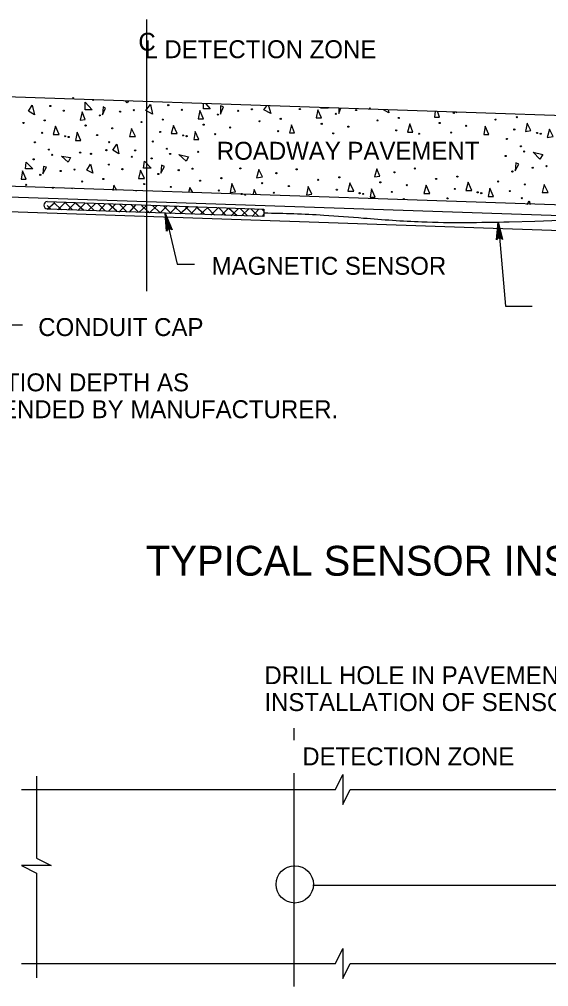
# Model space of a CAD drawing. Extents: x 2709 to 3899, y 22 to 1210.
# Drawn here: x 2819.9 to 2908.4, y 167.3 to 329.2 of the extents above; entities that cross this region are included whole.
import ezdxf

# ---------------------------------------------------------------- set-up
doc = ezdxf.new("R2010")
doc.units = 0
doc.layers.add('2', color=7, linetype='Continuous')
doc.layers.add('3', color=7, linetype='Continuous')

# ---------------------------------------------------------------- blocks, each defined once
blk = doc.blocks.new('RARROW')
at = {"layer": '3'}
blk.add_lwpolyline([(-2.2695, 0.285), (-2.184875, 0.12075), (0, 0), (-2.2695, 0.285), (-2.38575, 0.384625), (0, 0), (-2.183125, -0.108), (-2.262875, -0.2705), (0, 0), (-2.38575, -0.379125), (-2.262875, -0.2705)], dxfattribs=at)

msp = doc.modelspace()

# ---------------------------------------------------------------- linework, layer by layer
at = {"layer": '2'}
for p, q in [((2841.15, 329.17), (2841.15, 283.67)), ((2816.4, 299.54), (3040.28, 291.92)), ((2816.4, 297.04), (3040.28, 289.42)), ((2844.26, 296.74), (2846.28, 288.17)), ((2899.93, 295.3), (2901.15, 281.17)), ((2846.28, 288.17), (2849.15, 288.17)), ((2901.15, 281.17), (2905.65, 281.17)), ((2817.15, 278.04), (2820.4, 278.04)), ((2865.85, 208.54), (2865.85, 210.54)), ((2865.85, 167.29), (2865.85, 203.04)), ((2868.97, 184.29), (3023.97, 184.29))]:
    msp.add_line(p, q, dxfattribs=at)
for points in [[(2801.15, 316.79), (2948.65, 311.79), (2948.65, 296.79), (2801.15, 301.79), (2801.15, 301.79)], [(2837.9, 315.17), (2837.65, 315.54)], [(2838.15, 315.54), (2837.9, 315.17)], [(2850.65, 314.17), (2850.65, 315.04)], [(2851.78, 314.17), (2850.65, 314.17)], [(2851.03, 315.04), (2851.78, 314.17)], [(2860.78, 314.04), (2861.28, 314.67)], [(2861.53, 314.67), (2861.9, 313.42)], [(2870.28, 314.29), (2870.28, 314.42)], [(2871.53, 314.29), (2870.28, 314.29)], [(2871.53, 314.42), (2871.53, 314.29)], [(2873.28, 314.29), (2873.28, 313.42)], [(2873.28, 313.42), (2873.65, 314.29)], [(2861.9, 313.42), (2860.78, 314.04)], [(2881.65, 313.54), (2880.78, 314.04)], [(2881.53, 314.04), (2881.65, 313.54)], [(2889.4, 313.79), (2889.28, 312.79)], [(2889.28, 312.79), (2890.15, 312.79)], [(2890.15, 312.79), (2889.78, 313.79)], [(2892.9, 313.67), (2892.9, 313.54)], [(2892.9, 313.54), (2893.03, 313.67)], [(2835.65, 301.42), (2835.53, 300.54)], [(2836.15, 300.54), (2835.65, 301.42)], [(2855.4, 301.67), (2855.15, 300.17)], [(2856.03, 300.29), (2855.4, 301.67)], [(2868.15, 301.17), (2867.9, 299.79)], [(2868.78, 299.92), (2868.15, 301.17)], [(2828.65, 300.92), (2828.65, 300.79)], [(2828.78, 300.79), (2828.65, 300.92)], [(2839.4, 300.54), (2839.4, 300.42)], [(2839.4, 300.42), (2839.4, 300.54)], [(2848.4, 301.04), (2848.15, 300.17)], [(2848.9, 300.17), (2848.4, 301.04)], [(2855.15, 300.17), (2856.03, 300.29)], [(2859.15, 300.67), (2858.9, 299.79)], [(2859.53, 299.79), (2859.15, 300.67)], [(2867.9, 299.79), (2868.78, 299.92)], [(2878.78, 300.79), (2878.53, 299.42)], [(2879.4, 299.42), (2878.78, 300.79)], [(2824.53, 298.67), (2860.78, 297.42), (2860.78, 296.17), (2824.53, 297.42), (2824.53, 297.42)], [(2824.53, 297.42), (2825.78, 298.54)], [(2825.15, 297.42), (2824.53, 298.04)], [(2826.9, 297.29), (2825.65, 298.54)], [(2826.28, 297.29), (2827.53, 298.54)], [(2828.78, 297.29), (2827.53, 298.54)], [(2828.03, 297.29), (2829.15, 298.42)], [(2830.65, 297.17), (2829.28, 298.42)], [(2829.65, 297.17), (2830.9, 298.42)], [(2832.4, 297.17), (2831.15, 298.42)], [(2831.4, 297.17), (2832.65, 298.42)], [(2834.28, 297.04), (2833.03, 298.29)], [(2833.15, 297.04), (2834.28, 298.29)], [(2834.78, 297.04), (2836.03, 298.29)], [(2836.15, 297.04), (2834.78, 298.29)], [(2836.53, 296.92), (2837.78, 298.17)], [(2837.9, 296.92), (2836.65, 298.17)], [(2838.28, 296.92), (2839.4, 298.17)], [(2839.78, 296.92), (2838.53, 298.17)], [(2839.9, 296.92), (2841.15, 298.04)], [(2841.65, 296.79), (2840.28, 298.04)], [(2841.65, 296.79), (2842.9, 298.04)], [(2843.4, 296.79), (2842.15, 298.04)], [(2843.4, 296.79), (2844.53, 297.92)], [(2845.28, 296.67), (2844.03, 297.92)], [(2845.03, 296.67), (2846.28, 297.92)], [(2847.03, 296.67), (2845.78, 297.92)], [(2878.53, 299.42), (2879.4, 299.42)], [(2904.78, 298.17), (2905.15, 298.79)], [(2905.15, 298.79), (2905.28, 298.17)], [(2846.78, 296.67), (2848.03, 297.79)], [(2848.9, 296.54), (2847.65, 297.79)], [(2848.53, 296.54), (2849.65, 297.79)], [(2850.78, 296.54), (2849.4, 297.79)], [(2850.15, 296.54), (2851.4, 297.67)], [(2852.53, 296.42), (2851.28, 297.67)], [(2851.9, 296.42), (2853.15, 297.67)], [(2854.4, 296.42), (2853.15, 297.67)], [(2853.65, 296.42), (2854.78, 297.54)], [(2856.28, 296.29), (2854.9, 297.54)], [(2855.28, 296.29), (2856.53, 297.54)], [(2858.03, 296.29), (2856.78, 297.54)], [(2857.03, 296.29), (2858.28, 297.54)], [(2859.9, 296.17), (2858.65, 297.42)], [(2858.78, 296.17), (2859.9, 297.42)], [(2860.78, 297.04), (2860.4, 297.42)], [(2860.53, 296.17), (2860.78, 296.54)], [(2820.22, 200.29), (2872.72, 200.29), (2873.97, 202.79), (2873.97, 197.79), (2875.22, 200.29), (2925.22, 200.29), (2926.47, 202.79), (2926.47, 197.79), (2927.72, 200.29), (2977.72, 200.29), (2978.97, 202.79), (2978.97, 197.79), (2980.22, 200.29), (3026.47, 200.29)], [(2822.72, 202.54), (2822.72, 188.79), (2825.22, 187.54), (2820.22, 187.54), (2822.72, 186.29), (2822.72, 168.79)], [(2820.22, 171.16), (2872.72, 171.16), (2873.97, 173.66), (2873.97, 168.66), (2875.22, 171.16), (2925.22, 171.16), (2926.47, 173.66), (2926.47, 168.66), (2927.72, 171.16), (2977.72, 171.16), (2978.97, 173.66), (2978.97, 168.66), (2980.22, 171.16), (3026.47, 171.16)]]:
    msp.add_lwpolyline(points, dxfattribs=at)
for points in [[(2821.4, 313.79), (2822.03, 314.79), (2822.4, 313.17)], [(2830.9, 314.04), (2830.9, 315.29), (2832.03, 314.04)], [(2834.28, 314.29), (2833.9, 314.54), (2833.78, 313.17)], [(2841.03, 313.92), (2841.78, 314.92), (2842.15, 313.29)], [(2854.03, 314.54), (2853.53, 314.67), (2853.53, 313.29)], [(2830.4, 313.67), (2830.03, 312.29), (2830.9, 312.42)], [(2850.03, 313.92), (2849.78, 312.54), (2850.65, 312.54)], [(2869.78, 314.04), (2869.53, 312.67), (2870.4, 312.67)], [(2825.9, 311.29), (2825.53, 309.92), (2826.53, 309.92)], [(2838.65, 310.92), (2838.28, 309.54), (2839.28, 309.54)], [(2845.65, 311.42), (2845.28, 310.04), (2846.28, 310.04)], [(2865.4, 311.54), (2865.03, 310.17), (2865.9, 310.17)], [(2885.15, 311.67), (2884.78, 310.29), (2885.65, 310.29)], [(2897.78, 311.29), (2897.53, 309.92), (2898.4, 309.92)], [(2904.78, 311.79), (2904.53, 310.42), (2905.4, 310.54)], [(2829.53, 310.29), (2829.28, 308.92), (2830.15, 308.92)], [(2849.28, 310.42), (2849.03, 309.04), (2849.9, 309.04)], [(2908.53, 310.79), (2908.15, 309.42), (2909.15, 309.54)], [(2835.53, 307.29), (2836.15, 308.29), (2836.53, 306.67)], [(2828.4, 306.04), (2828.03, 305.29), (2826.9, 306.29)], [(2848.15, 306.17), (2847.78, 305.42), (2846.53, 306.54)], [(2907.4, 306.54), (2906.9, 305.79), (2905.78, 306.92)], [(2820.9, 304.17), (2821.03, 305.29), (2822.15, 304.17)], [(2824.4, 304.42), (2823.9, 304.54), (2823.78, 303.29)], [(2831.15, 303.92), (2831.78, 304.92), (2832.15, 303.42)], [(2840.65, 304.29), (2840.78, 305.42), (2841.9, 304.29)], [(2844.15, 304.54), (2843.65, 304.79), (2843.53, 303.42)], [(2903.4, 304.92), (2902.9, 305.17), (2902.78, 303.79)], [(2820.4, 303.79), (2820.15, 302.42), (2821.03, 302.42)], [(2840.15, 303.92), (2839.78, 302.54), (2840.78, 302.54)], [(2859.9, 304.04), (2859.53, 302.67), (2860.53, 302.79)], [(2879.65, 304.17), (2879.28, 302.79), (2880.15, 302.92)], [(2875.15, 301.79), (2874.78, 300.42), (2875.78, 300.42)], [(2887.9, 301.42), (2887.53, 300.04), (2888.53, 300.04)], [(2894.9, 301.92), (2894.53, 300.54), (2895.53, 300.54)], [(2907.65, 301.54), (2907.28, 300.17), (2908.28, 300.17)], [(2898.53, 300.92), (2898.28, 299.54), (2899.15, 299.54)]]:
    msp.add_lwpolyline(points, close=True, dxfattribs=at)
for centre, radius in [((2828.88, 315.97), 0.0919), ((2832.2, 315.69), 0.0919), ((2825.05, 314.66), 0.0919), ((2839.02, 313.97), 0.0919), ((2844.78, 314.8), 0.0919), ((2847.03, 314.02), 0.0919), ((2858.76, 314.11), 0.0919), ((2866.77, 314.16), 0.0919), ((2876.19, 313.99), 0.0919), ((2878.49, 314.25), 0.0919), ((2827.3, 313.88), 0.0919), ((2833.32, 313.09), 0.0919), ((2836.72, 313.72), 0.0919), ((2843.85, 312.39), 0.0919), ((2853.05, 313.23), 0.0919), ((2856.46, 313.86), 0.0919), ((2863.58, 312.52), 0.0919), ((2872.79, 313.36), 0.0919), ((2883.32, 312.66), 0.0919), ((2892.52, 313.5), 0.0919), ((2899.51, 312.39), 0.0919), ((2903.05, 312.8), 0.0919), ((2820.57, 311.83), 0.0919), ((2824.11, 312.25), 0.0919), ((2830.96, 311.41), 0.0919), ((2835.41, 310.93), 0.0919), ((2840.3, 311.97), 0.0919), ((2850.69, 311.55), 0.0919), ((2855.14, 311.07), 0.0919), ((2860.04, 312.11), 0.0919), ((2870.43, 311.69), 0.0919), ((2874.88, 311.2), 0.0919), ((2879.77, 312.25), 0.0919), ((2890.16, 311.83), 0.0919), ((2894.61, 311.34), 0.0919), ((2902.64, 310.73), 0.0919), ((2823.7, 310.18), 0.0919), ((2827.52, 309.6), 0.0919), ((2828.12, 309.47), 0.0919), ((2832.89, 309.81), 0.0919), ((2843.43, 310.32), 0.0919), ((2847.25, 309.74), 0.0919), ((2847.85, 309.61), 0.0919), ((2852.62, 309.95), 0.0919), ((2863.17, 310.45), 0.0919), ((2872.36, 310.09), 0.0919), ((2882.9, 310.59), 0.0919), ((2886.72, 310.02), 0.0919), ((2892.09, 310.22), 0.0919), ((2901.41, 309.15), 0.0919), ((2906.45, 310.15), 0.0919), ((2907.05, 310.02), 0.0919), ((2822.48, 308.59), 0.0919), ((2834.9, 308.62), 0.0919), ((2842.21, 308.73), 0.0919), ((2844.55, 307.51), 0.0919), ((2903.75, 307.92), 0.0919), ((2824.82, 307.37), 0.0919), ((2825.36, 306.5), 0.0919), ((2830.04, 306.86), 0.0919), ((2831.86, 306.66), 0.0919), ((2834.42, 307.27), 0.0919), ((2838.68, 306.17), 0.0919), ((2839.24, 307.24), 0.0919), ((2841.99, 305.89), 0.0919), ((2845.1, 306.64), 0.0919), ((2849.78, 307), 0.0919), ((2901.2, 306.3), 0.0919), ((2904.3, 307.05), 0.0919), ((2822.26, 305.75), 0.0919), ((2834.85, 304.86), 0.0919), ((2905.72, 304.33), 0.0919), ((2908.03, 304.59), 0.0919), ((2823.38, 303.15), 0.0919), ((2826.78, 303.78), 0.0919), ((2829.09, 304.03), 0.0919), ((2837.1, 304.09), 0.0919), ((2843.12, 303.29), 0.0919), ((2846.52, 303.92), 0.0919), ((2848.82, 304.17), 0.0919), ((2856.83, 304.22), 0.0919), ((2862.85, 303.43), 0.0919), ((2866.25, 304.06), 0.0919), ((2873.38, 302.73), 0.0919), ((2882.59, 303.57), 0.0919), ((2885.99, 304.2), 0.0919), ((2893.12, 302.86), 0.0919), ((2902.32, 303.7), 0.0919), ((2821.02, 301.48), 0.0919), ((2830.37, 302.03), 0.0919), ((2833.91, 302.45), 0.0919), ((2840.76, 301.61), 0.0919), ((2845.21, 301.13), 0.0919), ((2850.1, 302.17), 0.0919), ((2853.65, 302.59), 0.0919), ((2860.49, 301.75), 0.0919), ((2864.94, 301.27), 0.0919), ((2869.84, 302.31), 0.0919), ((2880.23, 301.89), 0.0919), ((2884.67, 301.41), 0.0919), ((2889.57, 302.45), 0.0919), ((2899.96, 302.03), 0.0919), ((2904.41, 301.54), 0.0919), ((2825.47, 300.99), 0.0919), ((2853.23, 300.52), 0.0919), ((2857.05, 299.94), 0.0919), ((2857.65, 299.81), 0.0919), ((2862.42, 300.15), 0.0919), ((2872.97, 300.66), 0.0919), ((2876.78, 300.08), 0.0919), ((2877.38, 299.95), 0.0919), ((2882.15, 300.29), 0.0919), ((2892.7, 300.79), 0.0919), ((2896.52, 300.22), 0.0919), ((2897.12, 300.08), 0.0919), ((2901.89, 300.43), 0.0919), ((2884.17, 299.1), 0.0919), ((2891.48, 299.21), 0.0919), ((2903.9, 299.24), 0.0919), ((2865.93, 184.4), 3.12)]:
    msp.add_circle(centre, radius, dxfattribs=at)
msp.add_arc((2824.62, 298.06), 0.633, 100.3114, 261.7056, dxfattribs=at)
msp.add_spline([(2860.78, 296.79), (2870.78, 296.42), (2877.4, 295.92), (2887.15, 295.29), (2901.78, 295.29), (3039.53, 290.92), (3042.28, 290.54), (3046.03, 291.17), (3050.15, 290.92), (3050.15, 291.42), (3050.4, 293.79), (3051.65, 296.17), (3053.4, 297.67), (3055.65, 298.79), (3057.78, 299.42)], degree=3, dxfattribs=at)

# ---------------------------------------------------------------- block references
for p, xscale, yscale, rotation in [((2844.26, 296.74), 1.257434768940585, 1.3092961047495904, 103.6052684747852), ((2899.93, 295.3), 1.2574347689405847, 1.3092961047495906, 94.8622730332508)]:
    msp.add_blockref('RARROW', p, dxfattribs=dict(at, xscale=xscale, yscale=yscale, rotation=rotation))

# ---------------------------------------------------------------- texts
for s, height, p in [('C', 3, (2839.78, 323.92)), ('L DETECTION ZONE', 3, (2840.78, 322.67)), ('ROADWAY PAVEMENT', 3, (2852.9, 305.67)), ('MAGNETIC SENSOR', 3, (2852.03, 286.42)), ('CONDUIT CAP', 3, (2823.03, 276.17)), ('INSTALLATION DEPTH AS', 3, (2798.53, 266.92)), ('RECOMMENDED BY MANUFACTURER.', 3, (2798.53, 262.42)), ('TYPICAL SENSOR INSTALLATION - MAGNETIC DETECTOR', 5, (2841.03, 236.06)), ('DRILL HOLE IN PAVEMENT FOR', 3, (2860.85, 217.91)), ('INSTALLATION OF SENSOR', 3, (2860.85, 213.41)), ('  DETECTION ZONE', 3, (2864.96, 204.32))]:
    msp.add_text(s, height=height, dxfattribs=at).set_placement(p)

doc.saveas('drawing.dxf')
